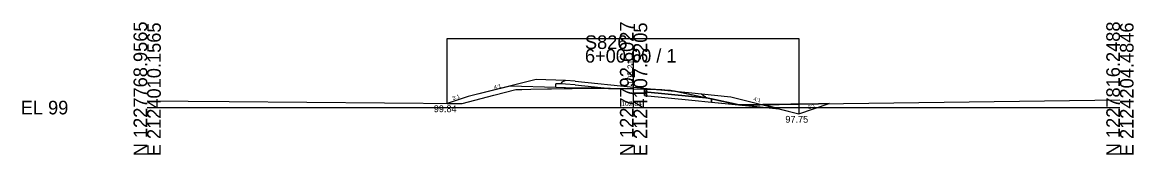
# Model space of a CAD drawing. Extents: x 2118382 to 2118616, y 1213030 to 1222057.
# Drawn here: x 2118381.9 to 2118610.4, y 1216530.1 to 1216557.3 of the extents above; entities that cross this region are included whole.
import ezdxf

# ---------------------------------------------------------------- set-up
doc = ezdxf.new("R2010")
doc.units = 0
for name, color, linetype in [('XS_CELL', 7, 'Continuous'), ('XS_M_DITCH', 7, 'Continuous'), ('XS_M_SHAPES_EARTHWORK', 7, 'Continuous'), ('XS_P_FINISHED_GRADE', 7, 'Continuous'), ('XS_P_FINISHED_GRADE_ELEV_TX', 7, 'Continuous'), ('XS_P_SUBGRADE_GRANULAR', 7, 'Continuous'), ('XS_P_SUBGRADE_LEVELING', 7, 'Continuous'), ('XS_P_SUBGRADE_PAVEMENT', 7, 'Continuous'), ('XS_P_TX_DCH', 7, 'Continuous'), ('XS_P_TX_FS_BS', 7, 'Continuous'), ('XS_X_GROUND', 7, 'Continuous'), ('XS_X_GROUND_TX', 7, 'Continuous')]:
    doc.layers.add(name, color=color, linetype=linetype)

msp = doc.modelspace()

# ---------------------------------------------------------------- linework, layer by layer
at = {"layer": 'XS_CELL'}
for p, q in [((2118507.6, 1216539.8), (2118507.6, 1216551.84)), ((2118407.6, 1216539.8), (2118507.6, 1216539.8)), ((2118507.6, 1216539.8), (2118607.6, 1216539.8))]:
    msp.add_line(p, q, dxfattribs=at)
at = {"layer": 'XS_M_DITCH'}
for p, q in [((2118469.31, 1216540.64), (2118469.31, 1216554.01)), ((2118469.31, 1216554.01), (2118541.6, 1216554.01)), ((2118541.6, 1216554.01), (2118541.6, 1216538.55))]:
    msp.add_line(p, q, dxfattribs=at)
at = {"layer": 'XS_M_SHAPES_EARTHWORK'}
for p, q in [((2118482.21, 1216544.22), (2118473.6, 1216542.07)), ((2118478.85, 1216542.32), (2118483.38, 1216543.51)), ((2118491.6, 1216543.95), (2118482.21, 1216544.22)), ((2118483.38, 1216543.51), (2118484.64, 1216543.53)), ((2118484.64, 1216543.53), (2118486.48, 1216543.58)), ((2118486.48, 1216543.58), (2118494.98, 1216543.75)), ((2118493.6, 1216543.89), (2118491.6, 1216543.95)), ((2118494.98, 1216543.76), (2118493.6, 1216543.89)), ((2118510.86, 1216543.56), (2118509.86, 1216543.6)), ((2118509.86, 1216543.6), (2118509.86, 1216543.04)), ((2118509.86, 1216543.04), (2118519.6, 1216542.08)), ((2118519.6, 1216542.08), (2118509.86, 1216543.04)), ((2118509.86, 1216543.04), (2118509.86, 1216542.29)), ((2118513.42, 1216543.44), (2118510.86, 1216543.56)), ((2118516.02, 1216543.18), (2118513.42, 1216543.44)), ((2118522.41, 1216541.83), (2118516.02, 1216543.18)), ((2118473.6, 1216542.07), (2118469.31, 1216540.64)), ((2118472.37, 1216540.61), (2118478.85, 1216542.32)), ((2118509.86, 1216542.29), (2118519.6, 1216541.33)), ((2118519.6, 1216542.08), (2118522.43, 1216541.8)), ((2118522.43, 1216541.8), (2118519.6, 1216542.08)), ((2118519.6, 1216541.33), (2118523.6, 1216540.93)), ((2118522.43, 1216541.8), (2118522.41, 1216541.83)), ((2118522.69, 1216541.78), (2118522.43, 1216541.8)), ((2118523.29, 1216541.65), (2118522.69, 1216541.78)), ((2118523.6, 1216541.58), (2118523.29, 1216541.65)), ((2118523.6, 1216540.93), (2118523.6, 1216541.58)), ((2118523.6, 1216541.58), (2118523.6, 1216540.93)), ((2118529.31, 1216540.37), (2118523.6, 1216541.58)), ((2118523.6, 1216540.93), (2118529.31, 1216540.37)), ((2118469.31, 1216540.64), (2118472.37, 1216540.61)), ((2118529.31, 1216540.37), (2118529.5, 1216540.33)), ((2118529.69, 1216540.34), (2118529.31, 1216540.37)), ((2118529.5, 1216540.33), (2118529.69, 1216540.34)), ((2118534.16, 1216540.41), (2118529.69, 1216540.34)), ((2118529.69, 1216540.34), (2118537.53, 1216539.56)), ((2118545.62, 1216540.59), (2118534.16, 1216540.41)), ((2118537.53, 1216539.56), (2118534.16, 1216540.41)), ((2118541.6, 1216538.55), (2118547.82, 1216540.61)), ((2118547.82, 1216540.61), (2118545.62, 1216540.59))]:
    msp.add_line(p, q, dxfattribs=at)
for points in [[(2118494.98, 1216543.75), (2118494.98, 1216543.76)], [(2118534.16, 1216540.41), (2118537.53, 1216539.56), (2118541.6, 1216538.55)]]:
    msp.add_lwpolyline(points, dxfattribs=at)
at = {"layer": 'XS_P_FINISHED_GRADE'}
for p, q in [((2118487.6, 1216545.56), (2118473.6, 1216542.07)), ((2118493.6, 1216545.39), (2118487.6, 1216545.56)), ((2118495.6, 1216545.2), (2118493.6, 1216545.39)), ((2118495.6, 1216545.2), (2118507.6, 1216544.01)), ((2118507.6, 1216544.01), (2118519.6, 1216542.83)), ((2118473.6, 1216542.07), (2118469.31, 1216540.64)), ((2118519.6, 1216542.83), (2118521.6, 1216542.63)), ((2118521.6, 1216542.63), (2118527.6, 1216542.04)), ((2118527.6, 1216542.04), (2118541.6, 1216538.55)), ((2118541.6, 1216538.55), (2118547.82, 1216540.61))]:
    msp.add_line(p, q, dxfattribs=at)
at = {"layer": 'XS_P_SUBGRADE_GRANULAR'}
for p, q in [((2118491.6, 1216543.95), (2118482.21, 1216544.22)), ((2118491.6, 1216543.95), (2118491.6, 1216544.7)), ((2118492.65, 1216544.67), (2118491.6, 1216544.7)), ((2118493.6, 1216543.89), (2118491.6, 1216543.95)), ((2118494.98, 1216543.76), (2118493.6, 1216543.89)), ((2118497.87, 1216543.81), (2118494.98, 1216543.76)), ((2118500.15, 1216543.78), (2118497.87, 1216543.81)), ((2118502.88, 1216543.73), (2118500.15, 1216543.78)), ((2118509.86, 1216542.29), (2118509.86, 1216543.04)), ((2118509.86, 1216542.29), (2118519.6, 1216541.33)), ((2118519.6, 1216541.33), (2118523.6, 1216540.93)), ((2118522.43, 1216541.8), (2118523.6, 1216541.68)), ((2118523.6, 1216540.93), (2118523.6, 1216541.68)), ((2118523.6, 1216540.93), (2118537.53, 1216539.56))]:
    msp.add_line(p, q, dxfattribs=at)
at = {"layer": 'XS_P_SUBGRADE_LEVELING'}
for q in [(2118502.88, 1216543.73), (2118509.86, 1216543.6)]:
    msp.add_line((2118507.6, 1216543.64), q, dxfattribs=at)
at = {"layer": 'XS_P_SUBGRADE_PAVEMENT'}
for p, q in [((2118493.6, 1216545.39), (2118492.85, 1216545.01)), ((2118492.85, 1216545.01), (2118492.65, 1216544.67)), ((2118493.6, 1216544.64), (2118492.65, 1216544.67)), ((2118495.6, 1216544.45), (2118493.6, 1216544.64)), ((2118495.6, 1216544.45), (2118502.88, 1216543.73)), ((2118509.86, 1216543.04), (2118509.86, 1216543.6)), ((2118509.86, 1216543.04), (2118519.6, 1216542.08)), ((2118519.6, 1216542.08), (2118522.43, 1216541.8)), ((2118521.6, 1216542.63), (2118522.25, 1216542.11)), ((2118522.25, 1216542.11), (2118522.43, 1216541.8))]:
    msp.add_line(p, q, dxfattribs=at)
at = {"layer": 'XS_X_GROUND'}
for p, q in [((2118478.85, 1216542.32), (2118483.38, 1216543.51)), ((2118483.38, 1216543.51), (2118484.64, 1216543.53)), ((2118484.64, 1216543.53), (2118486.48, 1216543.58)), ((2118486.48, 1216543.58), (2118496.74, 1216543.79)), ((2118496.74, 1216543.79), (2118497.87, 1216543.81)), ((2118497.87, 1216543.81), (2118502.44, 1216543.73)), ((2118502.44, 1216543.73), (2118503.64, 1216543.71)), ((2118503.64, 1216543.71), (2118507.6, 1216543.64)), ((2118507.6, 1216543.64), (2118509.86, 1216543.6)), ((2118509.86, 1216543.6), (2118510.86, 1216543.56)), ((2118510.86, 1216543.56), (2118515.2, 1216543.36)), ((2118515.2, 1216543.36), (2118523.29, 1216541.65)), ((2118407.6, 1216541.17), (2118424.47, 1216541.03)), ((2118424.47, 1216541.03), (2118472.37, 1216540.61)), ((2118472.37, 1216540.61), (2118478.85, 1216542.32)), ((2118523.29, 1216541.65), (2118529.5, 1216540.33)), ((2118545.62, 1216540.59), (2118607.6, 1216541.4)), ((2118529.5, 1216540.33), (2118545.62, 1216540.59))]:
    msp.add_line(p, q, dxfattribs=at)

# ---------------------------------------------------------------- texts
at = {"layer": 'XS_CELL'}
for s, p in [('N 1227768.9565', (2118407.6, 1216529.8)), ('E 2124010.1565', (2118410.4, 1216529.8)), ('N 1227792.6027', (2118507.6, 1216529.8)), ('E 2124107.3205', (2118510.4, 1216529.8)), ('N 1227816.2488', (2118607.6, 1216529.8)), ('E 2124204.4846', (2118610.4, 1216529.8))]:
    msp.add_text(s, height=2.8, rotation=90, dxfattribs=at).set_placement(p)
for s, p in [('S826', (2118497.6, 1216551.84)), ('6+00.00 / 1', (2118497.6, 1216549.04)), ('EL 99', (2118381.6, 1216538.4))]:
    msp.add_text(s, height=2.8, dxfattribs=at).set_placement(p)
at = {"layer": 'XS_P_FINISHED_GRADE_ELEV_TX'}
msp.add_text(' 103.21', height=1.25, rotation=90, dxfattribs=at).set_placement((2118507.6, 1216544.01))
at = {"layer": 'XS_P_TX_DCH'}
for s, p in [('99.84', (2118466.53, 1216538.86)), ('97.75', (2118538.81, 1216536.69))]:
    msp.add_text(s, height=1.4, dxfattribs=at).set_placement(p)
at = {"layer": 'XS_P_TX_FS_BS'}
for s, rotation, p in [('4:1', 14.0157, (2118478.97, 1216543.54)), ('3:1', 18.4087, (2118470.49, 1216541.3)), ('4:1', 345.9882, (2118532.18, 1216541.23)), ('3:1', 18.4038, (2118543.61, 1216539.41))]:
    msp.add_text(s, height=0.8, rotation=rotation, dxfattribs=at).set_placement(p)
at = {"layer": 'XS_X_GROUND_TX'}
msp.add_text('102.84', height=1, dxfattribs=at).set_placement((2118505.07, 1216540.11))

doc.saveas('drawing.dxf')
